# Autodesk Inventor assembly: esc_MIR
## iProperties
Shininess: 64.0
Length Units: 11272
Angle Units: 11279
Time Units: 11290
Mass Units: 11286
Length Display Precision: 3
Angle Display Precision: 2
Compacted: True
Part Number: esc_MIR
Document SubType Name: Assembly
Created: 2004-08
Designer: John Blackburn
Manufacturer: Standard
Standards Organization: Custom
Density: 0.0
Volumn: 0.0
Area: 0.0
PropertySet Name: Model Information
Control State: 0
Master: False
Checked Out: False
Author: John Blackburn
